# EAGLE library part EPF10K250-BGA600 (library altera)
EPF10K250 FLEX 10K family
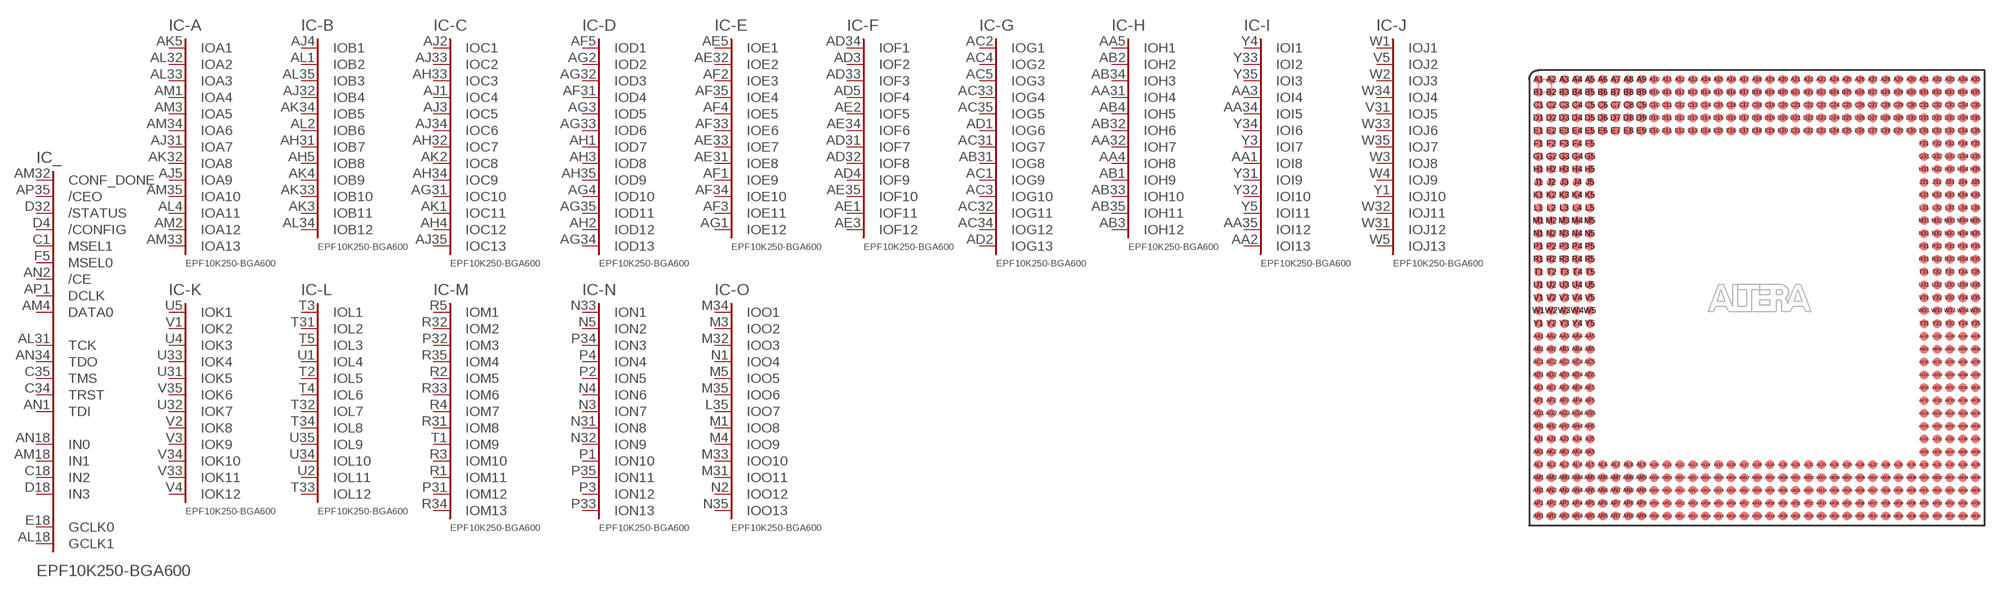
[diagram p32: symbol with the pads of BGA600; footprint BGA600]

Designator prefix IC; gates _=K240C -A=A13-600 -B=B12-600 -C=C13-600 -D=D13-600 -E=E12-600 -F=F12-600 -G=G13-600 -H=H12-600 -I=I13-600 -J=J13-600 -K=K12-600 -L=L12-600 -M=M13-600 -N=N13-600 -O=O13-600 -P=P14-600 -Q=Q14-600 -R=R12-600 -S=S13-600 -T=T14-600 -1=62-600 -2=122-600 -3=182-600 -4=242-600 -5=302-600 -6=361-600 -7=412-600 -8=471-600 -9=531-600 -10=583-600 -11=642-600 -12=702-600 -13=762-600 G1=GND G2=GND G3=GND G4=GND G5=GND G6=GND G7=GND G8=GND G9=GND G10=GND G11=GND G12=GND G13=GND G14=GND G15=GND G16=GND G17=GND G18=GND G19=GND G20=GND G21=GND G22=GND G23=GND G24=GND G25=GND G26=GND G27=GND G28=GND G29=GND G30=GND G31=GND G32=GND G33=GND G34=GND G35=GND G36=GND G37=GND G38=GND G39=GND G40=GND G41=GND G42=GND G43=GND G44=GND G45=GND G46=GND G47=GND G48=GND G49=GND G50=GND G51=GND G52=GND G53=GND G54=GND G55=GND G56=GND G57=GND G58=GND V1=VCCINT V2=VCCINT V3=VCCINT V4=VCCINT V5=VCCINT V6=VCCINT V7=VCCINT V8=VCCINT V9=VCCINT V10=VCCINT V11=VCCINT V12=VCCINT V13=VCCINT V14=VCCINT V15=VCCINT V16=VCCINT V17=VCCINT V18=VCCINT V19=VCCINT V20=VCCINT V21=VCCINT V22=VCCINT V23=VCCINT V24=VCCINT V25=VCCINT V26=VCCINT V27=VCCINT V28=VCCINT V29=VCCINT VO1=VCCIO VO2=VCCIO VO3=VCCIO VO4=VCCIO VO5=VCCIO VO6=VCCIO VO7=VCCIO VO8=VCCIO VO9=VCCIO VO10=VCCIO VO11=VCCIO VO12=VCCIO VO13=VCCIO VO14=VCCIO VO15=VCCIO VO16=VCCIO VO17=VCCIO VO18=VCCIO VO19=VCCIO VO20=VCCIO VO21=VCCIO VO22=VCCIO VO23=VCCIO VO24=VCCIO VO25=VCCIO VO26=VCCIO VO27=VCCIO VO28=VCCIO VO29=VCCIO

## EPF10K250-BGA600 (OC_FARNELL: unknown; OC_NEWARK: unknown)  [BGA600]
A1  G30:GND  pwr
A2  G31:GND  pwr
A3  G32:GND  pwr
A4  G33:GND  pwr
A5  G34:GND  pwr
A6  -1:IO12
A7  -1:IO52
A8  -2:IO83
A9  -2:IO111
A10  -3:IO151
A11  V13:VCC  pwr
A12  -4:IO213
A13  -5:IO252
A14  -5:IO291
A15  -6:IO313
A16  -6:IO352
A17  -7:IO381
A18  G35:GND  pwr
A19  V14:VCC  pwr
A20  VO15:VCCIO  pwr
A21  -8:IO453
A22  -9:IO493
A23  -9:IO523
A24  -10:IO553
A25  -10:IO572
A26  -11:IO613
A27  VO16:VCCIO  pwr
A28  -12:IO683
A29  -13:IO723
A30  -13:IO752
A31  G36:GND  pwr
A32  G37:GND  pwr
A33  G38:GND  pwr
A34  G39:GND  pwr
A35  G40:GND  pwr
AA1  -I:IOI8
AA2  -I:IOI13
AA3  -I:IOI4
AA4  -H:IOH8
AA5  -H:IOH1
AA31  -H:IOH4
AA32  -H:IOH7
AA33  V1:VCC  pwr
AA34  -I:IOI5
AA35  -I:IOI12
AB1  -H:IOH9
AB2  -H:IOH2
AB3  -H:IOH12
AB4  -H:IOH5
AB5  V2:VCC  pwr
AB31  -G:IOG8
AB32  -H:IOH6
AB33  -H:IOH10
AB34  -H:IOH3
AB35  -H:IOH11
AC1  -G:IOG9
AC2  -G:IOG1
AC3  -G:IOG10
AC4  -G:IOG2
AC5  -G:IOG3
AC31  -G:IOG7
AC32  -G:IOG11
AC33  -G:IOG4
AC34  -G:IOG12
AC35  -G:IOG5
AD1  -G:IOG6
AD2  -G:IOG13
AD3  -F:IOF2
AD4  -F:IOF9
AD5  -F:IOF4
AD31  -F:IOF7
AD32  -F:IOF8
AD33  -F:IOF3
AD34  -F:IOF1
AD35  V3:VCC  pwr
AE1  -F:IOF11
AE2  -F:IOF5
AE3  -F:IOF12
AE4  V4:VCC  pwr
AE5  -E:IOE1
AE31  -E:IOE8
AE32  -E:IOE2
AE33  -E:IOE7
AE34  -F:IOF6
AE35  -F:IOF10
AF1  -E:IOE9
AF2  -E:IOE3
AF3  -E:IOE11
AF4  -E:IOE5
AF5  -D:IOD1
AF31  -D:IOD4
AF32  V5:VCC  pwr
AF33  -E:IOE6
AF34  -E:IOE10
AF35  -E:IOE4
AG1  -E:IOE12
AG2  -D:IOD2
AG3  -D:IOD5
AG4  -D:IOD10
AG5  V6:VCC  pwr
AG31  -C:IOC10
AG32  -D:IOD3
AG33  -D:IOD6
AG34  -D:IOD13
AG35  -D:IOD11
AH1  -D:IOD7
AH2  -D:IOD12
AH3  -D:IOD8
AH4  -C:IOC12
AH5  -B:IOB8
AH31  -B:IOB7
AH32  -C:IOC7
AH33  -C:IOC3
AH34  -C:IOC9
AH35  -D:IOD9
AJ1  -C:IOC4
AJ2  -C:IOC1
AJ3  -C:IOC5
AJ4  -B:IOB1
AJ5  -A:IOA9
AJ31  -A:IOA7
AJ32  -B:IOB4
AJ33  -C:IOC2
AJ34  -C:IOC6
AJ35  -C:IOC13
AK1  -C:IOC11
AK2  -C:IOC8
AK3  -B:IOB11
AK4  -B:IOB9
AK5  -A:IOA1
AK31  V7:VCC  pwr
AK32  -A:IOA8
AK33  -B:IOB10
AK34  -B:IOB5
AK35  V8:VCC  pwr
AL1  -B:IOB2
AL2  -B:IOB6
AL3  V9:VCC  pwr
AL4  -A:IOA11
AL5  VO1:VCCIO  pwr
AL6  G1:GND  pwr
AL7  -1:IO22
AL8  -1:IO51
AL9  -2:IO82
AL10  -2:IO121
AL11  -3:IO161
AL12  VO2:VCCIO  pwr
AL13  -4:IO222
AL14  -5:IO262
AL15  -5:IO292
AL16  -6:IO322
AL17  -6:IO361
AL18  _:GCLK1  in
AL19  -8:IO421
AL20  -8:IO451
AL21  -9:IO491
AL22  -9:IO521
AL23  -10:IO562
AL24  -11:IO601
AL25  -11:IO623
AL26  -12:IO651
AL27  -12:IO682
AL28  -13:IO722
AL29  -13:IO761
AL30  G2:GND  pwr
AL31  _:TCK
AL32  -A:IOA2
AL33  -A:IOA3
AL34  -B:IOB12
AL35  -B:IOB3
AM1  -A:IOA4
AM2  -A:IOA12
AM3  -A:IOA5
AM4  _:DATA0  in
AM5  VO3:VCCIO  pwr
AM6  G3:GND  pwr
AM7  -1:IO21
AM8  -1:IO61
AM9  -2:IO91
AM10  -3:IO131
AM11  -3:IO162
AM12  -4:IO192
AM13  -4:IO221
AM14  -5:IO261
AM15  -5:IO301
AM16  -6:IO332
AM17  -7:IO362
AM18  _:IN1  in
AM19  VO4:VCCIO  pwr
AM20  -8:IO442
AM21  -9:IO481
AM22  -9:IO522
AM23  -10:IO552
AM24  -10:IO582
AM25  -11:IO611
AM26  VO5:VCCIO  pwr
AM27  -12:IO681
AM28  -13:IO721
AM29  -13:IO751
AM30  G4:GND  pwr
AM31  VO6:VCCIO  pwr
AM32  _:CONF_DONE  in
AM33  -A:IOA13
AM34  -A:IOA6
AM35  -A:IOA10
AN1  _:TDI
AN2  _:/CE  in
AN3  VO7:VCCIO  pwr
AN4  VO8:VCCIO  pwr
AN5  G5:GND  pwr
AN6  G6:GND  pwr
AN7  -1:IO31
AN8  VO9:VCCIO  pwr
AN9  -2:IO102
AN10  -3:IO142
AN11  -3:IO172
AN12  -4:IO201
AN13  -4:IO232
AN14  -5:IO271
AN15  VO10:VCCIO  pwr
AN16  -6:IO342
AN17  -7:IO371
AN18  _:IN0  in
AN19  -7:IO411
AN20  -8:IO443
AN21  -9:IO482
AN22  -9:IO512
AN23  -10:IO542
AN24  -10:IO571
AN25  -11:IO602
AN26  -11:IO641
AN27  -12:IO671
AN28  -13:IO711
AN29  -13:IO741
AN30  G7:GND  pwr
AN31  G8:GND  pwr
AN32  VO11:VCCIO  pwr
AN33  VO12:VCCIO  pwr
AN34  _:TDO
AN35  G9:GND  pwr
AP1  _:DCLK  in
AP2  G10:GND  pwr
AP3  G11:GND  pwr
AP4  G12:GND  pwr
AP5  G13:GND  pwr
AP6  G14:GND  pwr
AP7  -1:IO41
AP8  -2:IO72
AP9  -2:IO101
AP10  -3:IO141
AP11  -3:IO181
AP12  -4:IO202
AP13  -4:IO241
AP14  -5:IO281
AP15  -6:IO312
AP16  -6:IO341
AP17  -7:IO382
AP18  -7:IO391
AP19  -7:IO402
AP20  -8:IO431
AP21  -8:IO462
AP22  -9:IO502
AP23  -10:IO541
AP24  V10:VCC  pwr
AP25  -11:IO592
AP26  -11:IO631
AP27  -12:IO661
AP28  -12:IO701
AP29  -13:IO742
AP30  G15:GND  pwr
AP31  G16:GND  pwr
AP32  G17:GND  pwr
AP33  G18:GND  pwr
AP34  VO13:VCCIO  pwr
AP35  _:/CEO  in
AR1  G19:GND  pwr
AR2  G20:GND  pwr
AR3  G21:GND  pwr
AR4  G22:GND  pwr
AR5  G23:GND  pwr
AR6  -1:IO11
AR7  -1:IO42
AR8  -2:IO81
AR9  -2:IO112
AR10  -3:IO152
AR11  V11:VCC  pwr
AR12  -4:IO211
AR13  -5:IO251
AR14  -5:IO282
AR15  -6:IO321
AR16  -6:IO351
AR17  -7:IO383
AR18  V12:VCC  pwr
AR19  -7:IO403
AR20  -8:IO422
AR21  -8:IO461
AR22  -9:IO501
AR23  VO14:VCCIO  pwr
AR24  -10:IO561
AR25  -10:IO583
AR26  -11:IO622
AR27  -12:IO662
AR28  -12:IO692
AR29  -13:IO731
AR30  G24:GND  pwr
AR31  G25:GND  pwr
AR32  G26:GND  pwr
AR33  G27:GND  pwr
AR34  G28:GND  pwr
AR35  G29:GND  pwr
B1  V15:VCC  pwr
B2  G41:GND  pwr
B3  G42:GND  pwr
B4  G43:GND  pwr
B5  G44:GND  pwr
B6  G45:GND  pwr
B7  -1:IO43
B8  -2:IO71
B9  -2:IO113
B10  -3:IO153
B11  -3:IO182
B12  -4:IO212
B13  -4:IO242
B14  -5:IO283
B15  -6:IO311
B16  -6:IO343
B17  -7:IO373
B18  V16:VCC  pwr
B19  -7:IO392
B20  -8:IO423
B21  -8:IO452
B22  -9:IO492
B23  -10:IO532
B24  -10:IO551
B25  -10:IO573
B26  -11:IO621
B27  -12:IO652
B28  -12:IO691
B29  -13:IO732
B30  -13:IO762
B31  G46:GND  pwr
B32  G47:GND  pwr
B33  G48:GND  pwr
B34  G49:GND  pwr
B35  G50:GND  pwr
C1  _:MSEL1  in
C2  VO17:VCCIO  pwr
C3  VO18:VCCIO  pwr
C4  VO19:VCCIO  pwr
C5  G51:GND  pwr
C6  G52:GND  pwr
C7  -1:IO32
C8  VO20:VCCIO  pwr
C9  -2:IO103
C10  -3:IO143
C11  -3:IO173
C12  -4:IO203
C13  -4:IO231
C14  -5:IO272
C15  VO21:VCCIO  pwr
C16  -6:IO331
C17  -7:IO372
C18  _:IN2  in
C19  -7:IO393
C20  -8:IO432
C21  -8:IO463
C22  -9:IO503
C23  VO22:VCCIO  pwr
C24  -10:IO563
C25  -11:IO591
C26  -11:IO633
C27  -12:IO663
C28  -12:IO693
C29  -13:IO733
C30  G53:GND  pwr
C31  G54:GND  pwr
C32  VO23:VCCIO  pwr
C33  VO24:VCCIO  pwr
C34  _:TRST
C35  _:TMS
D1  -T:IOT9
D2  -T:IOT5
D3  -T:IOT10
D4  _:/CONFIG  in
D5  VO25:VCCIO  pwr
D6  G55:GND  pwr
D7  -1:IO33
D8  -1:IO62
D9  -2:IO93
D10  -3:IO132
D11  -3:IO171
D12  -4:IO191
D13  -4:IO233
D14  -5:IO273
D15  -5:IO302
D16  -6:IO333
D17  -7:IO363
D18  _:IN3  in
D19  -7:IO401
D20  -8:IO433
D21  -8:IO471
D22  -9:IO511
D23  -9:IO531
D24  V17:VCC  pwr
D25  -11:IO603
D26  -11:IO632
D27  -12:IO673
D28  -12:IO702
D29  -13:IO743
D30  G56:GND  pwr
D31  VO26:VCCIO  pwr
D32  _:/STATUS  in
D33  -T:IOT13
D34  -T:IOT3
D35  -T:IOT11
E1  -S:IOS9
E2  V18:VCC  pwr
E3  -T:IOT8
E4  -T:IOT1
E5  VO27:VCCIO  pwr
E6  G57:GND  pwr
E7  -1:IO23
E8  -1:IO53
E9  -2:IO92
E10  -2:IO122
E11  -3:IO163
E12  VO28:VCCIO  pwr
E13  -4:IO223
E14  -5:IO263
E15  -5:IO293
E16  -6:IO323
E17  -6:IO353
E18  _:GCLK0  in
E19  -7:IO412
E20  -8:IO441
E21  -9:IO483
E22  -9:IO513
E23  -10:IO543
E24  -10:IO581
E25  -11:IO612
E26  -11:IO642
E27  -12:IO672
E28  -13:IO712
E29  -13:IO753
E30  G58:GND  pwr
E31  VO29:VCCIO  pwr
E32  -T:IOT2
E33  -T:IOT7
E34  -S:IOS10
E35  -S:IOS2
F1  -S:IOS6
F2  -S:IOS7
F3  -S:IOS1
F4  -T:IOT12
F5  _:MSEL0  in
F31  V19:VCC  pwr
F32  -T:IOT14
F33  -S:IOS11
F34  -S:IOS5
F35  V20:VCC  pwr
G1  -R:IOR5
G2  -R:IOR10
G3  -S:IOS13
G4  -S:IOS8
G5  -T:IOT4
G31  -T:IOT6
G32  -S:IOS3
G33  -R:IOR6
G34  -R:IOR4
G35  -R:IOR7
H1  V21:VCC  pwr
H2  -R:IOR8
H3  -R:IOR3
H4  -R:IOR1
H5  -S:IOS4
H31  -S:IOS12
H32  -R:IOR11
H33  -R:IOR2
H34  -Q:IOQ7
H35  -Q:IOQ1
J1  -Q:IOQ12
J2  -Q:IOQ2
J3  -Q:IOQ8
J4  -Q:IOQ3
J5  -R:IOR9
J31  -R:IOR12
J32  -Q:IOQ9
J33  -Q:IOQ4
J34  -Q:IOQ13
J35  -Q:IOQ14
K1  -P:IOP2
K2  -P:IOP8
K3  -Q:IOQ6
K4  -Q:IOQ10
K5  -Q:IOQ11
K31  -Q:IOQ5
K32  V22:VCC  pwr
K33  -P:IOP7
K34  -P:IOP9
K35  -P:IOP1
L1  -P:IOP10
L2  -P:IOP6
L3  -P:IOP11
L4  -P:IOP12
L5  -P:IOP4
L31  -P:IOP3
L32  -P:IOP13
L33  -P:IOP14
L34  -P:IOP5
L35  -O:IOO7
M1  -O:IOO8
M2  V23:VCC  pwr
M3  -O:IOO2
M4  -O:IOO9
M5  -O:IOO5
M31  -O:IOO11
M32  -O:IOO3
M33  -O:IOO10
M34  -O:IOO1
M35  -O:IOO6
N1  -O:IOO4
N2  -O:IOO12
N3  -N:ION7
N4  -N:ION6
N5  -N:ION2
N31  -N:ION8
N32  -N:ION9
N33  -N:ION1
N34  V24:VCC  pwr
N35  -O:IOO13
P1  -N:ION10
P2  -N:ION5
P3  -N:ION12
P4  -N:ION4
P5  V25:VCC  pwr
P31  -M:IOM12
P32  -M:IOM3
P33  -N:ION13
P34  -N:ION3
P35  -N:ION11
R1  -M:IOM11
R2  -M:IOM5
R3  -M:IOM10
R4  -M:IOM7
R5  -M:IOM1
R31  -M:IOM8
R32  -M:IOM2
R33  -M:IOM6
R34  -M:IOM13
R35  -M:IOM4
T1  -M:IOM9
T2  -L:IOL5
T3  -L:IOL1
T4  -L:IOL6
T5  -L:IOL3
T31  -L:IOL2
T32  -L:IOL7
T33  -L:IOL12
T34  -L:IOL8
T35  V26:VCC  pwr
U1  -L:IOL4
U2  -L:IOL11
U3  V27:VCC  pwr
U4  -K:IOK3
U5  -K:IOK1
U31  -K:IOK5
U32  -K:IOK7
U33  -K:IOK4
U34  -L:IOL10
U35  -L:IOL9
V1  -K:IOK2
V2  -K:IOK8
V3  -K:IOK9
V4  -K:IOK12
V5  -J:IOJ2
V31  -J:IOJ5
V32  V28:VCC  pwr
V33  -K:IOK11
V34  -K:IOK10
V35  -K:IOK6
W1  -J:IOJ1
W2  -J:IOJ3
W3  -J:IOJ8
W4  -J:IOJ9
W5  -J:IOJ13
W31  -J:IOJ12
W32  -J:IOJ11
W33  -J:IOJ6
W34  -J:IOJ4
W35  -J:IOJ7
Y1  -J:IOJ10
Y2  V29:VCC  pwr
Y3  -I:IOI7
Y4  -I:IOI1
Y5  -I:IOI11
Y31  -I:IOI9
Y32  -I:IOI10
Y33  -I:IOI2
Y34  -I:IOI6
Y35  -I:IOI3

## Footprint BGA600 (pad centres in mm)
Ball Grid Array
smd 0.9 x 0.9: A1 -21.59,21.59; A2 -20.32,21.59; A3 -19.05,21.59; A4 -17.78,21.59; A5 -16.51,21.59; A6 -15.24,21.59; A7 -13.97,21.59; A8 -12.7,21.59; A9 -11.43,21.59; A10 -10.16,21.59; A11 -8.89,21.59; A12 -7.62,21.59; A13 -6.35,21.59; A14 -5.08,21.59; A15 -3.81,21.59; A16 -2.54,21.59; A17 -1.27,21.59; A18 0,21.59; A19 1.27,21.59; A20 2.54,21.59; A21 3.81,21.59; A22 5.08,21.59; A23 6.35,21.59; A24 7.62,21.59; A25 8.89,21.59; A26 10.16,21.59; A27 11.43,21.59; A28 12.7,21.59; A29 13.97,21.59; A30 15.24,21.59; A31 16.51,21.59; A32 17.78,21.59; A33 19.05,21.59; A34 20.32,21.59; A35 21.59,21.59; AA1 -21.59,-3.81; AA2 -20.32,-3.81; AA3 -19.05,-3.81; AA4 -17.78,-3.81; AA5 -16.51,-3.81; AA31 16.51,-3.81; AA32 17.78,-3.81; AA33 19.05,-3.81; AA34 20.32,-3.81; AA35 21.59,-3.81; AB1 -21.59,-5.08; AB2 -20.32,-5.08; AB3 -19.05,-5.08; AB4 -17.78,-5.08; AB5 -16.51,-5.08; AB31 16.51,-5.08; AB32 17.78,-5.08; AB33 19.05,-5.08; AB34 20.32,-5.08; AB35 21.59,-5.08; AC1 -21.59,-6.35; AC2 -20.32,-6.35; AC3 -19.05,-6.35; AC4 -17.78,-6.35; AC5 -16.51,-6.35; AC31 16.51,-6.35; AC32 17.78,-6.35; AC33 19.05,-6.35; AC34 20.32,-6.35; AC35 21.59,-6.35; AD1 -21.59,-7.62; AD2 -20.32,-7.62; AD3 -19.05,-7.62; AD4 -17.78,-7.62; AD5 -16.51,-7.62; AD31 16.51,-7.62; AD32 17.78,-7.62; AD33 19.05,-7.62; AD34 20.32,-7.62; AD35 21.59,-7.62; AE1 -21.59,-8.89; AE2 -20.32,-8.89; AE3 -19.05,-8.89; AE4 -17.78,-8.89; AE5 -16.51,-8.89; AE31 16.51,-8.89; AE32 17.78,-8.89; AE33 19.05,-8.89; AE34 20.32,-8.89; AE35 21.59,-8.89; AF1 -21.59,-10.16; AF2 -20.32,-10.16; AF3 -19.05,-10.16; AF4 -17.78,-10.16; AF5 -16.51,-10.16; AF31 16.51,-10.16; AF32 17.78,-10.16; AF33 19.05,-10.16; AF34 20.32,-10.16; AF35 21.59,-10.16; AG1 -21.59,-11.43; AG2 -20.32,-11.43; AG3 -19.05,-11.43; AG4 -17.78,-11.43; AG5 -16.51,-11.43; AG31 16.51,-11.43; AG32 17.78,-11.43; AG33 19.05,-11.43; AG34 20.32,-11.43; AG35 21.59,-11.43; AH1 -21.59,-12.7; AH2 -20.32,-12.7; AH3 -19.05,-12.7; AH4 -17.78,-12.7; AH5 -16.51,-12.7; AH31 16.51,-12.7; AH32 17.78,-12.7; AH33 19.05,-12.7; AH34 20.32,-12.7; AH35 21.59,-12.7; AJ1 -21.59,-13.97; AJ2 -20.32,-13.97; AJ3 -19.05,-13.97; AJ4 -17.78,-13.97; AJ5 -16.51,-13.97; AJ31 16.51,-13.97; AJ32 17.78,-13.97; AJ33 19.05,-13.97; AJ34 20.32,-13.97; AJ35 21.59,-13.97; AK1 -21.59,-15.24; AK2 -20.32,-15.24; AK3 -19.05,-15.24; AK4 -17.78,-15.24; AK5 -16.51,-15.24; AK31 16.51,-15.24; AK32 17.78,-15.24; AK33 19.05,-15.24; AK34 20.32,-15.24; AK35 21.59,-15.24; AL1 -21.59,-16.51; AL2 -20.32,-16.51; AL3 -19.05,-16.51; AL4 -17.78,-16.51; AL5 -16.51,-16.51; AL6 -15.24,-16.51; AL7 -13.97,-16.51; AL8 -12.7,-16.51; AL9 -11.43,-16.51; AL10 -10.16,-16.51; AL11 -8.89,-16.51; AL12 -7.62,-16.51; AL13 -6.35,-16.51; AL14 -5.08,-16.51; AL15 -3.81,-16.51; AL16 -2.54,-16.51; AL17 -1.27,-16.51; AL18 0,-16.51; AL19 1.27,-16.51; AL20 2.54,-16.51; AL21 3.81,-16.51; AL22 5.08,-16.51; AL23 6.35,-16.51; AL24 7.62,-16.51; AL25 8.89,-16.51; AL26 10.16,-16.51; AL27 11.43,-16.51; AL28 12.7,-16.51; AL29 13.97,-16.51; AL30 15.24,-16.51; AL31 16.51,-16.51; AL32 17.78,-16.51; AL33 19.05,-16.51; AL34 20.32,-16.51; AL35 21.59,-16.51; AM1 -21.59,-17.78; AM2 -20.32,-17.78; AM3 -19.05,-17.78; AM4 -17.78,-17.78; AM5 -16.51,-17.78; AM6 -15.24,-17.78; AM7 -13.97,-17.78; AM8 -12.7,-17.78; AM9 -11.43,-17.78; AM10 -10.16,-17.78; AM11 -8.89,-17.78; AM12 -7.62,-17.78; AM13 -6.35,-17.78; AM14 -5.08,-17.78; AM15 -3.81,-17.78; AM16 -2.54,-17.78; AM17 -1.27,-17.78; AM18 0,-17.78; AM19 1.27,-17.78; AM20 2.54,-17.78; AM21 3.81,-17.78; AM22 5.08,-17.78; AM23 6.35,-17.78; AM24 7.62,-17.78; AM25 8.89,-17.78; AM26 10.16,-17.78; AM27 11.43,-17.78; AM28 12.7,-17.78; AM29 13.97,-17.78; AM30 15.24,-17.78; AM31 16.51,-17.78; AM32 17.78,-17.78; AM33 19.05,-17.78; AM34 20.32,-17.78; AM35 21.59,-17.78; AN1 -21.59,-19.05; AN2 -20.32,-19.05; AN3 -19.05,-19.05; AN4 -17.78,-19.05; AN5 -16.51,-19.05; AN6 -15.24,-19.05; AN7 -13.97,-19.05; AN8 -12.7,-19.05; AN9 -11.43,-19.05; AN10 -10.16,-19.05; AN11 -8.89,-19.05; AN12 -7.62,-19.05; AN13 -6.35,-19.05; AN14 -5.08,-19.05; AN15 -3.81,-19.05; AN16 -2.54,-19.05; AN17 -1.27,-19.05; AN18 0,-19.05; AN19 1.27,-19.05; AN20 2.54,-19.05; AN21 3.81,-19.05; AN22 5.08,-19.05; AN23 6.35,-19.05; AN24 7.62,-19.05; AN25 8.89,-19.05; AN26 10.16,-19.05; AN27 11.43,-19.05; AN28 12.7,-19.05; AN29 13.97,-19.05; AN30 15.24,-19.05; AN31 16.51,-19.05; AN32 17.78,-19.05; AN33 19.05,-19.05; AN34 20.32,-19.05; AN35 21.59,-19.05; AP1 -21.59,-20.32; AP2 -20.32,-20.32; AP3 -19.05,-20.32; AP4 -17.78,-20.32; AP5 -16.51,-20.32; AP6 -15.24,-20.32; AP7 -13.97,-20.32; AP8 -12.7,-20.32; AP9 -11.43,-20.32; AP10 -10.16,-20.32; AP11 -8.89,-20.32; AP12 -7.62,-20.32; AP13 -6.35,-20.32; AP14 -5.08,-20.32; AP15 -3.81,-20.32; AP16 -2.54,-20.32; AP17 -1.27,-20.32; AP18 0,-20.32; AP19 1.27,-20.32; AP20 2.54,-20.32; AP21 3.81,-20.32; AP22 5.08,-20.32; AP23 6.35,-20.32; AP24 7.62,-20.32; AP25 8.89,-20.32; AP26 10.16,-20.32; AP27 11.43,-20.32; AP28 12.7,-20.32; AP29 13.97,-20.32; AP30 15.24,-20.32; AP31 16.51,-20.32; AP32 17.78,-20.32; AP33 19.05,-20.32; AP34 20.32,-20.32; AP35 21.59,-20.32; AR1 -21.59,-21.59; AR2 -20.32,-21.59; AR3 -19.05,-21.59; AR4 -17.78,-21.59; AR5 -16.51,-21.59; AR6 -15.24,-21.59; AR7 -13.97,-21.59; AR8 -12.7,-21.59; AR9 -11.43,-21.59; AR10 -10.16,-21.59; AR11 -8.89,-21.59; AR12 -7.62,-21.59; AR13 -6.35,-21.59; AR14 -5.08,-21.59; AR15 -3.81,-21.59; AR16 -2.54,-21.59; AR17 -1.27,-21.59; AR18 0,-21.59; AR19 1.27,-21.59; AR20 2.54,-21.59; AR21 3.81,-21.59; AR22 5.08,-21.59; AR23 6.35,-21.59; AR24 7.62,-21.59; AR25 8.89,-21.59; AR26 10.16,-21.59; AR27 11.43,-21.59; AR28 12.7,-21.59; AR29 13.97,-21.59; AR30 15.24,-21.59; AR31 16.51,-21.59; AR32 17.78,-21.59; AR33 19.05,-21.59; AR34 20.32,-21.59; AR35 21.59,-21.59; B1 -21.59,20.32; B2 -20.32,20.32; B3 -19.05,20.32; B4 -17.78,20.32; B5 -16.51,20.32; B6 -15.24,20.32; B7 -13.97,20.32; B8 -12.7,20.32; B9 -11.43,20.32; B10 -10.16,20.32; B11 -8.89,20.32; B12 -7.62,20.32; B13 -6.35,20.32; B14 -5.08,20.32; B15 -3.81,20.32; B16 -2.54,20.32; B17 -1.27,20.32; B18 0,20.32; B19 1.27,20.32; B20 2.54,20.32; B21 3.81,20.32; B22 5.08,20.32; B23 6.35,20.32; B24 7.62,20.32; B25 8.89,20.32; B26 10.16,20.32; B27 11.43,20.32; B28 12.7,20.32; B29 13.97,20.32; B30 15.24,20.32; B31 16.51,20.32; B32 17.78,20.32; B33 19.05,20.32; B34 20.32,20.32; B35 21.59,20.32; C1 -21.59,19.05; C2 -20.32,19.05; C3 -19.05,19.05; C4 -17.78,19.05; C5 -16.51,19.05; C6 -15.24,19.05; C7 -13.97,19.05; C8 -12.7,19.05; C9 -11.43,19.05; C10 -10.16,19.05; C11 -8.89,19.05; C12 -7.62,19.05; C13 -6.35,19.05; C14 -5.08,19.05; C15 -3.81,19.05; C16 -2.54,19.05; C17 -1.27,19.05; C18 0,19.05; C19 1.27,19.05; C20 2.54,19.05; C21 3.81,19.05; C22 5.08,19.05; C23 6.35,19.05; C24 7.62,19.05; C25 8.89,19.05; C26 10.16,19.05; C27 11.43,19.05; C28 12.7,19.05; C29 13.97,19.05; C30 15.24,19.05; C31 16.51,19.05; C32 17.78,19.05; C33 19.05,19.05; C34 20.32,19.05; C35 21.59,19.05; D1 -21.59,17.78; D2 -20.32,17.78; D3 -19.05,17.78; D4 -17.78,17.78; D5 -16.51,17.78; D6 -15.24,17.78; D7 -13.97,17.78; D8 -12.7,17.78; D9 -11.43,17.78; D10 -10.16,17.78; D11 -8.89,17.78; D12 -7.62,17.78; D13 -6.35,17.78; D14 -5.08,17.78; D15 -3.81,17.78; D16 -2.54,17.78; D17 -1.27,17.78; D18 0,17.78; D19 1.27,17.78; D20 2.54,17.78; D21 3.81,17.78; D22 5.08,17.78; D23 6.35,17.78; D24 7.62,17.78; D25 8.89,17.78; D26 10.16,17.78; D27 11.43,17.78; D28 12.7,17.78; D29 13.97,17.78; D30 15.24,17.78; D31 16.51,17.78; D32 17.78,17.78; D33 19.05,17.78; D34 20.32,17.78; D35 21.59,17.78; E1 -21.59,16.51; E2 -20.32,16.51; E3 -19.05,16.51; E4 -17.78,16.51; E5 -16.51,16.51; E6 -15.24,16.51; E7 -13.97,16.51; E8 -12.7,16.51; E9 -11.43,16.51; E10 -10.16,16.51; E11 -8.89,16.51; E12 -7.62,16.51; E13 -6.35,16.51; E14 -5.08,16.51; E15 -3.81,16.51; E16 -2.54,16.51; E17 -1.27,16.51; E18 0,16.51; E19 1.27,16.51; E20 2.54,16.51; E21 3.81,16.51; E22 5.08,16.51; E23 6.35,16.51; E24 7.62,16.51; E25 8.89,16.51; E26 10.16,16.51; E27 11.43,16.51; E28 12.7,16.51; E29 13.97,16.51; E30 15.24,16.51; E31 16.51,16.51; E32 17.78,16.51; E33 19.05,16.51; E34 20.32,16.51; E35 21.59,16.51; F1 -21.59,15.24; F2 -20.32,15.24; F3 -19.05,15.24; F4 -17.78,15.24; F5 -16.51,15.24; F31 16.51,15.24; F32 17.78,15.24; F33 19.05,15.24; F34 20.32,15.24; F35 21.59,15.24; G1 -21.59,13.97; G2 -20.32,13.97; G3 -19.05,13.97; G4 -17.78,13.97; G5 -16.51,13.97; G31 16.51,13.97; G32 17.78,13.97; G33 19.05,13.97; G34 20.32,13.97; G35 21.59,13.97; H1 -21.59,12.7; H2 -20.32,12.7; H3 -19.05,12.7; H4 -17.78,12.7; H5 -16.51,12.7; H31 16.51,12.7; H32 17.78,12.7; H33 19.05,12.7; H34 20.32,12.7; H35 21.59,12.7; J1 -21.59,11.43; J2 -20.32,11.43; J3 -19.05,11.43; J4 -17.78,11.43; J5 -16.51,11.43; J31 16.51,11.43; J32 17.78,11.43; J33 19.05,11.43; J34 20.32,11.43; J35 21.59,11.43; K1 -21.59,10.16; K2 -20.32,10.16; K3 -19.05,10.16; K4 -17.78,10.16; K5 -16.51,10.16; K31 16.51,10.16; K32 17.78,10.16; K33 19.05,10.16; K34 20.32,10.16; K35 21.59,10.16; L1 -21.59,8.89; L2 -20.32,8.89; L3 -19.05,8.89; L4 -17.78,8.89; L5 -16.51,8.89; L31 16.51,8.89; L32 17.78,8.89; L33 19.05,8.89; L34 20.32,8.89; L35 21.59,8.89; M1 -21.59,7.62; M2 -20.32,7.62; M3 -19.05,7.62; M4 -17.78,7.62; M5 -16.51,7.62; M31 16.51,7.62; M32 17.78,7.62; M33 19.05,7.62; M34 20.32,7.62; M35 21.59,7.62; N1 -21.59,6.35; N2 -20.32,6.35; N3 -19.05,6.35; N4 -17.78,6.35; N5 -16.51,6.35; N31 16.51,6.35; N32 17.78,6.35; N33 19.05,6.35; N34 20.32,6.35; N35 21.59,6.35; P1 -21.59,5.08; P2 -20.32,5.08; P3 -19.05,5.08; P4 -17.78,5.08; P5 -16.51,5.08; P31 16.51,5.08; P32 17.78,5.08; P33 19.05,5.08; P34 20.32,5.08; P35 21.59,5.08; R1 -21.59,3.81; R2 -20.32,3.81; R3 -19.05,3.81; R4 -17.78,3.81; R5 -16.51,3.81; R31 16.51,3.81; R32 17.78,3.81; R33 19.05,3.81; R34 20.32,3.81; R35 21.59,3.81; T1 -21.59,2.54; T2 -20.32,2.54; T3 -19.05,2.54; T4 -17.78,2.54; T5 -16.51,2.54; T31 16.51,2.54; T32 17.78,2.54; T33 19.05,2.54; T34 20.32,2.54; T35 21.59,2.54; U1 -21.59,1.27; U2 -20.32,1.27; U3 -19.05,1.27; U4 -17.78,1.27; U5 -16.51,1.27; U31 16.51,1.27; U32 17.78,1.27; U33 19.05,1.27; U34 20.32,1.27; U35 21.59,1.27; V1 -21.59,0; V2 -20.32,0; V3 -19.05,0; V4 -17.78,0; V5 -16.51,0; V31 16.51,0; V32 17.78,0; V33 19.05,0; V34 20.32,0; V35 21.59,0; W1 -21.59,-1.27; W2 -20.32,-1.27; W3 -19.05,-1.27; W4 -17.78,-1.27; W5 -16.51,-1.27; W31 16.51,-1.27; W32 17.78,-1.27; W33 19.05,-1.27; W34 20.32,-1.27; W35 21.59,-1.27; Y1 -21.59,-2.54; Y2 -20.32,-2.54; Y3 -19.05,-2.54; Y4 -17.78,-2.54; Y5 -16.51,-2.54; Y31 16.51,-2.54; Y32 17.78,-2.54; Y33 19.05,-2.54; Y34 20.32,-2.54; Y35 21.59,-2.54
